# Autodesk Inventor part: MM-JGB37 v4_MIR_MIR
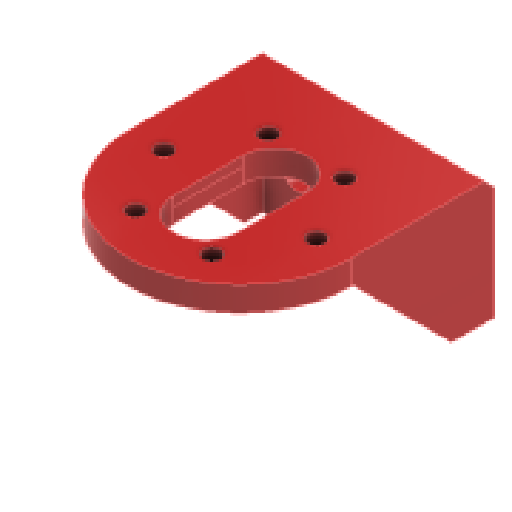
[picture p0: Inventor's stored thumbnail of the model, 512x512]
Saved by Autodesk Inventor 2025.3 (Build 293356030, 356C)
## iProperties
Created: 2024-01
Part Number: MM-JGB37 v4_MIR_MIR
Material: Plastica PET
Document SubType Name: Modeling
Designer: R5800u
Density: 1.541 g/cm^3
Appearance: Rosso
Sending System: Autodesk Translation Framework v12.14.0.127
Preprocessor: ST-DEVELOPER v20
Title: MM-JGB37 v4.step
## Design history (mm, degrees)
derived "MM-JGB37 v4_MIR.ipt"
  sketch "Schizzo1"
    geometry: L1 (0, -42.5)-(0, 0) reference; L2 (40, -42.5)-(0, -42.5) reference; L3 (40, -42.5)-(40, 0) reference; L4 (0, 0)-(40, 0) reference; 1 further point
  sketch "Schizzo6"
    geometry: L1 (-2.5, -5)-(-2.5, 24) reference; L2 (42.5, 24)-(42.5, -5) reference; L3 (-2.5, -5)-(42.5, -5) reference; L4 (42.5, -5)-(42.5, 0) reference; L5 (42.5, 0)-(-2.5, 0) reference; L6 (-2.5, 0)-(-2.5, -5) reference; L7 (0, 0)-(40, 0) reference; L8 (0, -5)-(0, 0) reference; L9 (40, -5)-(0, -5) reference; L10 (40, -5)-(40, 0) reference; 1 further point
  sketch "Schizzo7"
    geometry: L1 (5, -5)-(29, -5) reference; L2 (29, 0)-(29, -5) reference; L3 (0, 0)-(29, 0) reference; L4 (0, 0)-(0, -44.5) reference; L5 (5, -44.5)-(0, -44.5) reference; L6 (5, -44.5)-(5, -5) reference; L7 (27.973, -5.631)-(5, -28.604) reference; A1 r 1.151 centre (29, -6.151) between (29, -5) and (27.973, -5.631) reference; 1 further point
  sketch "Schizzo8"
    geometry: L1 (10, -180.5)-(10, 19.5) reference; L2 (0, 29.5)-(300, 29.5) reference; L3 (45, 0)-(0, 0) reference; L4 (45, 0)-(45, 15.067) reference; L5 (0, 16.481)-(0, 38.869) reference; L6 (0, 0)-(0, 15.067) reference; 8 further points
  node "Piano di lavoro1"
sketch "Schizzo9"
  geometry: L1 (41, 44.5)-(-4, 44.5) reference; L2 (-4, 16.481)-(-4, 38.869) reference; L3 (41, 44.5)-(-4, 44.5); L4 (-4, 44.5)-(-4, 19.5); L5 (-4, 19.5)-(41, 19.5); L6 (41, 19.5)-(41, 44.5); L7 (-4, 19.5)-(46.418, 19.5); L8 (46.418, 19.5)-(46.418, -7.181); L9 (46.418, -7.181)-(-4, -7.181); L10 (-4, -7.181)-(-4, 19.5); 3 further points
  constraints: 16 end point, 4 parallel, 2 horizontal, 2 perpendicular, 1 point on line
  dimensions: "d1" = 25 distance of L4.end L3.end
extrude "Estrusione1" cut sketch "Schizzo9" extent not by distance; stored distance "d2" = 0; taper "d3" = 0 deg
feature "Solido1::MM-JGB37 v4_MIR.ipt" dims "d0" = 10
tag "Lavorazione contrassegno1"
sketch "Schizzo3"
  geometry: L1 (20, 0)-(20, 29) reference; L2 (-20, 29)-(20, 29) reference; L3 (-20, 29)-(-20, 0) reference; L4 (-6.5, -7)-(-6.5, 7) reference; L5 (6.5, 7)-(6.5, -7) reference; C1 r 1.75 at (15.5, 0) reference; C2 r 1.75 at (-7.75, -13.423) reference; C3 r 1.75 at (7.75, -13.423) reference; C4 r 1.75 at (7.75, 13.423) reference; C5 r 1.75 at (-15.5, 0) reference; C6 r 1.75 at (-7.75, 13.423) reference; A1 r 20 centre (0, 0) between (-20, 0) and (20, 0) reference; A2 r 6.5 centre (0, 7) between (6.5, 7) and (-6.5, 7) reference; A3 r 6.5 centre (0, -7) between (-6.5, -7) and (6.5, -7) reference; 1 further point
sketch "Schizzo5"
  geometry: L1 (20, 0)-(20, 29) reference; L2 (20, 29)-(-20, 29) reference; L3 (-20, 29)-(-20, 0) reference; L4 (6.5, 7)-(6.5, -7) reference; L5 (-6.5, -7)-(-6.5, 7) reference; L6 (-22.5, 0)-(-22.5, 31.5) reference; L7 (-22.5, 31.5)-(22.5, 31.5) reference; L8 (22.5, 31.5)-(22.5, 0) reference; L9 (22.5, 29)-(20, 29) reference; L10 (-22.5, 29)-(-20, 29) reference; C1 r 1.75 at (-7.75, 13.423) reference; C2 r 1.75 at (-15.5, 0) reference; C3 r 1.75 at (7.75, 13.423) reference; C4 r 1.75 at (7.75, -13.423) reference; C5 r 1.75 at (-7.75, -13.423) reference; C6 r 1.75 at (15.5, 0) reference; A1 r 20 centre (0, 0) between (-20, 0) and (20, 0) reference; A2 r 6.5 centre (0, -7) between (-6.5, -7) and (6.5, -7) reference; A3 r 6.5 centre (0, 7) between (6.5, 7) and (-6.5, 7) reference; A4 r 22.5 centre (0, 0) between (-22.5, 0) and (22.5, 0) reference; 1 further point
node "Solido1"
